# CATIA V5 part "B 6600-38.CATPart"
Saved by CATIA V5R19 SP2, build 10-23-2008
Part number: B 6600-38
Bounding box of the stored display mesh (mm): x -59.975 to 59.975, y -59.975 to 59.975, z 0 to 216
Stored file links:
  C:\Users\Bora\Desktop\3D Katı model\B serisi\B 6600\B 6600-38.CATPart
  C:\Program Files\Dassault Systemes\B19\intel_a\reffiles\standard\MetricThickPitch.txt
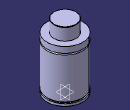
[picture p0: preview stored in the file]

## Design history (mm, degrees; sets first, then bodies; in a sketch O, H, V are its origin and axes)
Body1 (main body)
  Sketch1 on yz-plane, origin (0, 0, 0), H (0, 1, 0), V (0, 0, 1)
    point P3 (37.5, 215)
    point P5 (37.5, 215)
    point P10 (60, 150)
    point P11 (60, 155)
    point P13 (60, 155)
    point P14 (60, 150)
    line L1 (60, 0) -> (60, 8)
    line L2 (37.5, 215) -> (37.5, 175)
    arc A1 centre (36.5, 215) radius 1 from (37.5, 215) to (36.5, 216) ccw
    line L3 (56, 13) -> (56, 8)
    line L4 (60, 13) -> (60, 150)
    line L5 (60, 155) -> (60, 175)
    arc A2 centre (60, 152.5) radius 2.5 from (60, 155) to (60, 150) ccw
    line L6 (36.5, 216) -> (0, 216)
    point P15 (0, 216)
    line L7 (37.5, 175) -> (60, 175)
    line L8 (0, 0) -> (60, 0)
    line L9 (56, 13) -> (60, 13)
    line L10 (56, 8) -> (60, 8)
    coincidence: P15 V, P3 P5, P10 P14, P11 P13
    tangency: L6 A1
    horizontal: L7 H, L8 H, L9 H, L10 H
  Shaft1: profile Sketch1, axis Sketch1.V, angle 360
  Sketch2 on face of Shaft1 from Sketch1.L8, origin (0, 0, 0), H (1, 0, 0), V (0, -1, 0)
    point P1 (40, 0)
    distance P1 V = 40
  Hole1: placed by Sketch2, at (40, 0, 0) direction (0, 0, 1), diameter 8.376, depth 16, threaded "M10", thread diameter 10, thread depth 16, pitch 1.5
  CircPattern1: of Hole1, instances 4, angular step 90, axis from xy-plane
